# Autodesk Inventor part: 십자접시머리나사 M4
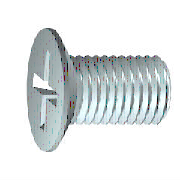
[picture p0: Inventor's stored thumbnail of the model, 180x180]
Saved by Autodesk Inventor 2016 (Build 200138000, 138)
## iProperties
IsCustomPart: 0
Created: 2012-02
Part Number: 십자접시머리나사 M4
Material: 강철, 연강
Description: 십자 오목 머리 나사
Document SubType Name: Modeling
Standard: KS B 1023
Designer: mduedu
Standards Organization: KS
Language: ko-KR
Size Designation: A  M 4 x 12 - H
Categories: <MemberInstance><Categories><Category DisplayName="조임쇠" InternalName="e4da775c-781d-43d5-af7c-5136215cf5a6" Mnemonic="FSTN"><Category DisplayName="볼트" InternalN
Density: 7.86 g/cm^3
Mass: 1.50481 g
Surface Area: 2.78563 cm^2
Volume: 0.191451 cm^3
Appearance: 주황색
Author: mduedu
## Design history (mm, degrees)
body "Solid1"
sketch "스케치1"
  geometry: L1 (2.6, 0)-(12, 0); L2 (12, 0)-(12, 2); L3 (12, 2)-(4.1, 2); L4 (4.1, 2)-(3.671, 1.785); L5 (3.671, 1.785)-(2.7, 1.785); L6 (0, 4.2)-(0, 2.4); L7 (0, 2.4)-(1.801, 1.502); L8 (1.801, 1.502)-(2.6, 0); L9 (-2.4, 0)-(14.4, 0) reference; L10 (0, -0.84)-(0, 5.04) reference; L11 (0, 4.2)-(0.285, 4.2); L12 (0.285, 4.2)-(2.7, 1.785); L13 (4.1, 2)-(2.485, 2)
  constraints: 22 end point, 3 parallel, 3 perpendicular, 2 collinear, 1 horizontal, 1 point on line
  dimensions: "d1" = 7.9 distance of L2.end L3.end (= GEL); "d2" = 4 diameter of L3 L1 (= GD); "d3" = 3.57058 diameter of L5 L1 (= BDM); "d4" = 4.8 diameter of L6.end L1 (= SDM); "d5" = 26.5 deg angle of L7 L1; "d6" = 62 deg angle of L8 L1; "d7" = 2.6 distance from line of L1.start L6 (= INTI); "d8" = 0.42941 horizontal distance of L4.end L3.end (= GAL); "d12" = 8.4 diameter of L11 L1 (= KOD); "d13" = 45 deg angle of L12 L1 (= 0.5 x SEWI); "d15" = 12 distance between parallel lines of L2 L6 (= NLG); "d24" = 2.7 distance from line of L5.end L6 (= KOH)
revolve "본체" stored, may be unused: angle "d16" = 90 deg
sketch "스케치2"
  geometry: L1 (0, 2.4)-(0, 0); L2 (0, 0)-(2.4, 0); L3 (0, 0)-(1.697, 1.697); L4 (0.312, 2.38)-(0.408, 0.734); L5 (2.38, 0.312)-(0.734, 0.408); L6 (0, -5.88)-(0, 5.88) reference; L7 (-5.88, 0)-(5.88, 0) reference; L8 (2.38, -0.312)-(0.734, -0.408); L9 (0.312, -2.38)-(0.408, -0.734); L10 (-0.312, -2.38)-(-0.408, -0.734); L11 (-2.38, -0.312)-(-0.734, -0.408); L12 (-2.38, 0.312)-(-0.734, 0.408); L13 (-0.312, 2.38)-(-0.408, 0.734); A1 r 0.72 centre (0, 0) between (0.72, 0) and (0, 0.72); A2 r 0.84 centre (0, 0) between (0.84, 0) and (0, 0.84); A3 r 2.4 centre (0, 0) between (2.38, 0.312) and (0.312, 2.38); A4 r 2.4 centre (0, 0) between (0.312, 2.38) and (0, 2.4); A5 r 2.4 centre (0, 0) between (2.4, 0) and (2.38, 0.312); A6 r 2.4 centre (0, 0) between (0, -2.4) and (0.312, -2.38); A7 r 2.4 centre (0, 0) between (0.312, -2.38) and (2.38, -0.312); A8 r 2.4 centre (0, 0) between (2.38, -0.312) and (2.4, 0); A9 r 2.4 centre (0, 0) between (0, 2.4) and (-0.312, 2.38); A10 r 2.4 centre (0, 0) between (-0.312, 2.38) and (-2.38, 0.312); A11 r 2.4 centre (0, 0) between (-2.38, 0.312) and (-2.4, 0); A12 r 2.4 centre (0, 0) between (-2.4, 0) and (-2.38, -0.312); A13 r 2.4 centre (0, 0) between (-2.38, -0.312) and (-0.312, -2.38); A14 r 2.4 centre (0, 0) between (-0.312, -2.38) and (0, -2.4); A15 r 0.347 centre (0.755, 0.755) between (0.408, 0.734) and (0.734, 0.408); A16 r 0.347 centre (0.755, -0.755) between (0.734, -0.408) and (0.408, -0.734); A17 r 0.347 centre (-0.755, -0.755) between (-0.408, -0.734) and (-0.734, -0.408); A18 r 0.347 centre (-0.755, 0.755) between (-0.734, 0.408) and (-0.408, 0.734); 3 further points
  constraints: 41 point on circle, 22 end point, 22 symmetric about line, 18 centre point, 11 coincident, 4 point on line, 3 tangent, 2 collinear, 1 perpendicular, 1 vertical, 19 other
  dimensions: "d17" = 1.44 diameter of A1 (= 0.3 x SDM); "d18" = 1.68 diameter of A2 (= 0.35 x SDM); "d19" = 4.8 diameter of A3 (= SDM); "d20" = 45 deg angle of L3 L2; "d21" = 0.3115 distance from line of L4.start L1 (= 0.5 x SBR)
extrude "슬롯" join sketch "스케치2" taper "d22" = 5 deg; stored distance "d79" = 25.4
fillet "모깎기1" dims "d23" = 0.1246 (= 0.2 x SBR)
feature "스레드" dims "d10" = 7.9 (= GEL), "d11" = 0
chamfer "모따기1" distance "d25" = 0.42941 (= -0.5 x SPD + 0.5 x GD); stored, may be unused: second distance "d26" = 0.21471 (= 0.5 x GAL), angle "d88" = 45 deg
workplane "Work Plane2"
other parameters: "NLG" = 12 [user parameter; used in 1 equation term], "GEL" = 7.9 [user parameter; used in 2 equation terms], "GAL" = 0.42941 (= 0.61345 x PTC) [user parameter; used in 3 equation terms], "SPD" = 3.14117 (= NND - 1.2269 x PTC) [user parameter; used in 1 equation term], "KOD" = 8.4 [user parameter; used in 1 equation term], "KOH" = 2.7 [user parameter; used in 1 equation term], "SBR" = 0.623 [user parameter; used in 2 equation terms], "INTI" = 2.6 [user parameter; used in 1 equation term], "SDM" = 4.8 [user parameter; used in 5 equation terms], "GD" = 4 (= NND) [user parameter; used in 2 equation terms], "BDM" = 3.57058 (= NND - GAL) [user parameter; used in 1 equation term], "SEWI" = 90 deg [user parameter; used in 1 equation term], "d9" = 4.8 (= SDM), "d27" = 0, "d91" = 0, "d92" = 0, "GUL" = 0.42941 (= 0.61345 x PTC) [user parameter], "TOA" = 30 deg [user parameter], "EPV" = 4.7 [user parameter], "THREADDIA" = 4 [user parameter; used in 1 equation term], "TPU" = 14.28571 (computed from PTC) [user parameter], "PTC" = 0.7 [user parameter; used in 5 equation terms], "NND" = 4 [user parameter; used in 3 equation terms], "GD1" = 3.14117 (= THREADDIA - 1.2269 x PTC) [user parameter]
